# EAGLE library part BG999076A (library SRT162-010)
1.5 inch LCD
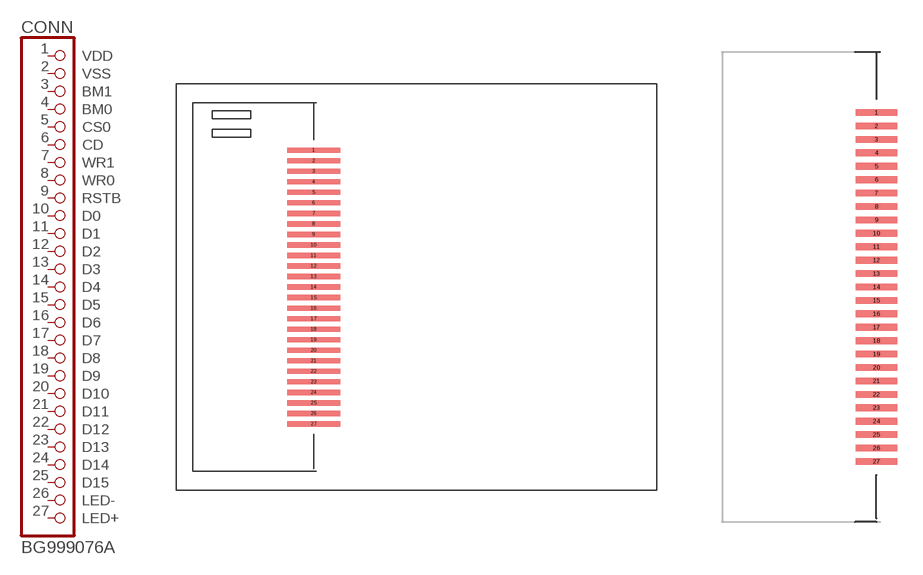
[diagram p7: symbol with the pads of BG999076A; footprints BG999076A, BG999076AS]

Designator prefix CONN

## BG999076A  [BG999076A]
1  VDD  pas
2  VSS  pas
3  BM1  pas
4  BM0  pas
5  CS0  pas
6  CD  pas
7  WR1  pas
8  WR0  pas
9  RSTB  pas
10  D0  pas
11  D1  pas
12  D2  pas
13  D3  pas
14  D4  pas
15  D5  pas
16  D6  pas
17  D7  pas
18  D8  pas
19  D9  pas
20  D10  pas
21  D11  pas
22  D12  pas
23  D13  pas
24  D14  pas
25  D15  pas
26  LED-  pas
27  LED+  pas

## BG999076AS  [BG999076AS]
Pads as for BG999076A

## Footprint BG999076A (pad centres in mm)
smd 4 x 0.4: 1 0,10.4; 2 0,9.6; 3 0,8.8; 4 0,8; 5 0,7.2; 6 0,6.4; 7 0,5.6; 8 0,4.8; 9 0,4; 10 0,3.2; 11 0,2.4; 12 0,1.6; 13 0,0.8; 14 0,0; 15 0,-0.8; 16 0,-1.6; 17 0,-2.4; 18 0,-3.2; 19 0,-4; 20 0,-4.8; 21 0,-5.6; 22 0,-6.4; 23 0,-7.2; 24 0,-8; 25 0,-8.8; 26 0,-9.6; 27 0,-10.4

## Footprint BG999076AS (pad centres in mm)
smd 2.5 x 0.4: 1 0,10.4; 2 0,9.6; 3 0,8.8; 4 0,8; 5 0,7.2; 6 0,6.4; 7 0,5.6; 8 0,4.8; 9 0,4; 10 0,3.2; 11 0,2.4; 12 0,1.6; 13 0,0.8; 14 0,0; 15 0,-0.8; 16 0,-1.6; 17 0,-2.4; 18 0,-3.2; 19 0,-4; 20 0,-4.8; 21 0,-5.6; 22 0,-6.4; 23 0,-7.2; 24 0,-8; 25 0,-8.8; 26 0,-9.6; 27 0,-10.4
